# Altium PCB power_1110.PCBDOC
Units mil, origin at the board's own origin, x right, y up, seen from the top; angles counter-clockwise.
Board outline 4331.71 x 2363.2 mil, 4 copper layers (TOP, GND02, POWER03, BOTTOM), stack 28.8 mil thick; 43 components, 17 nets, 191 pads, 290 vias.
Unrouted connection lines stored in the file: 131.
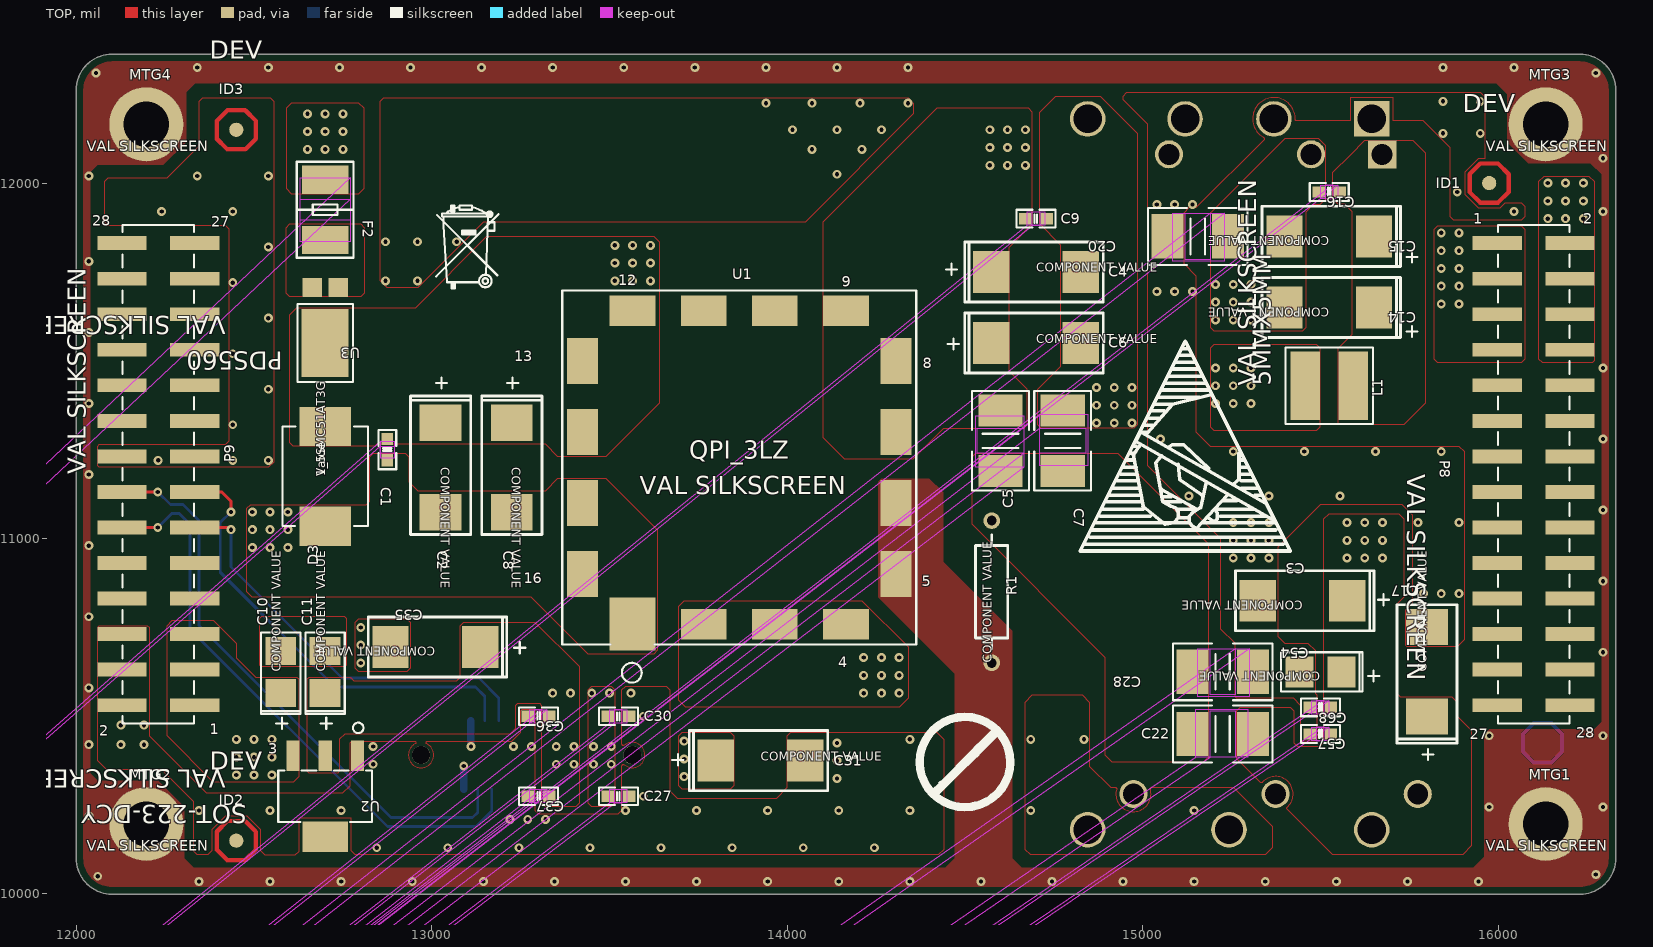
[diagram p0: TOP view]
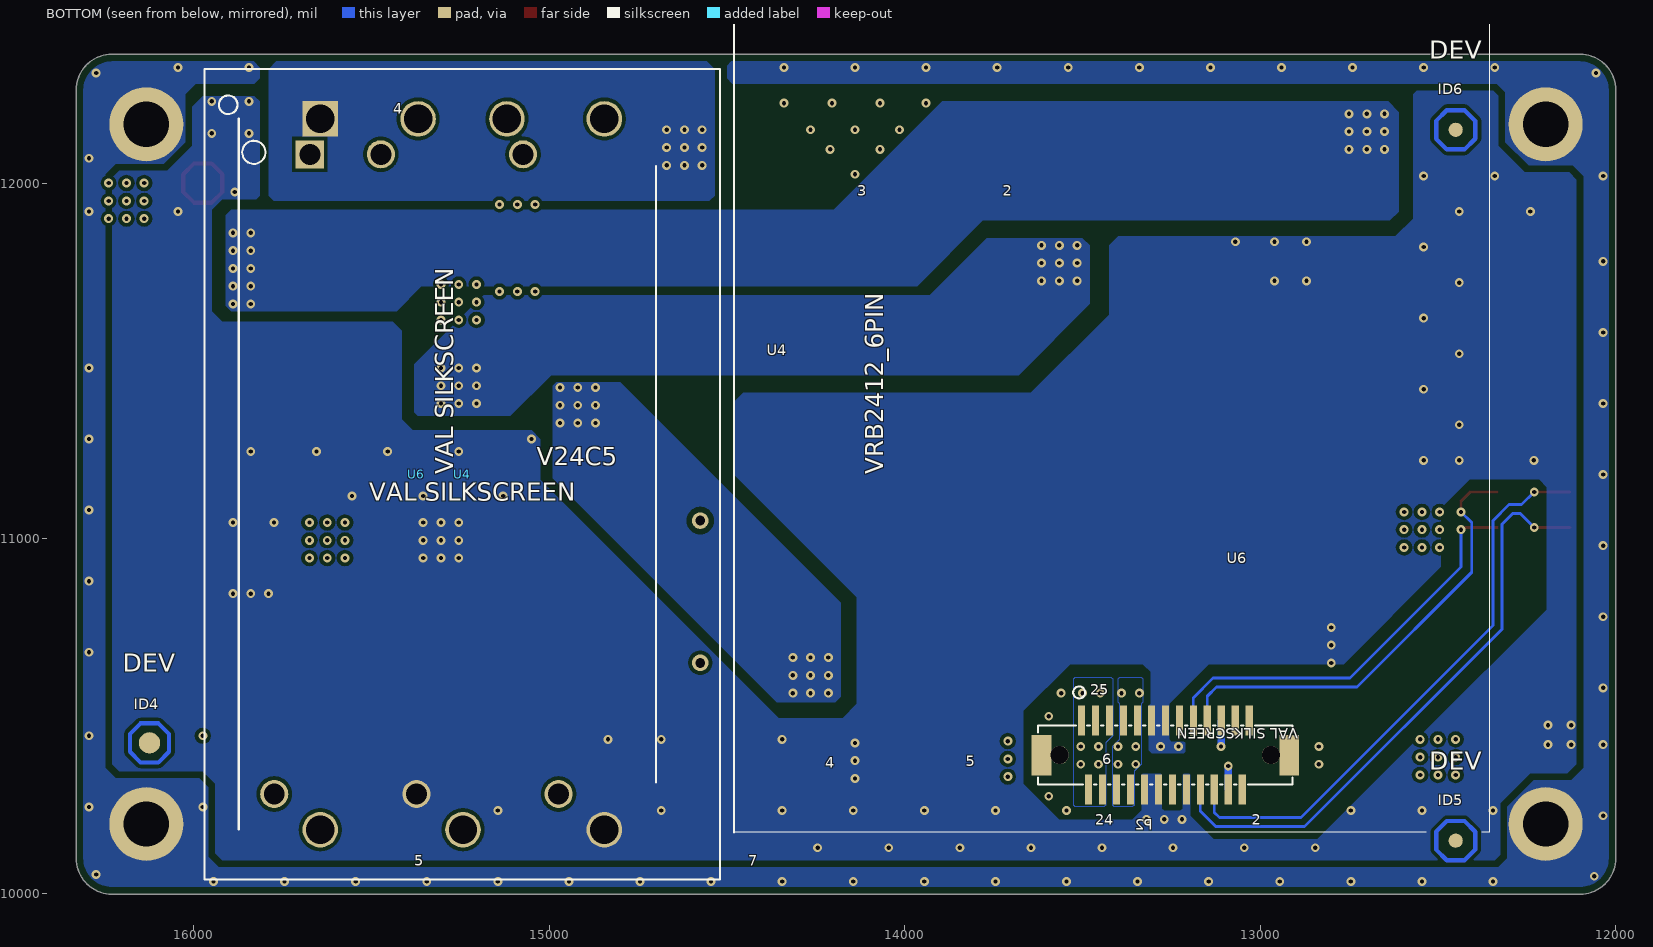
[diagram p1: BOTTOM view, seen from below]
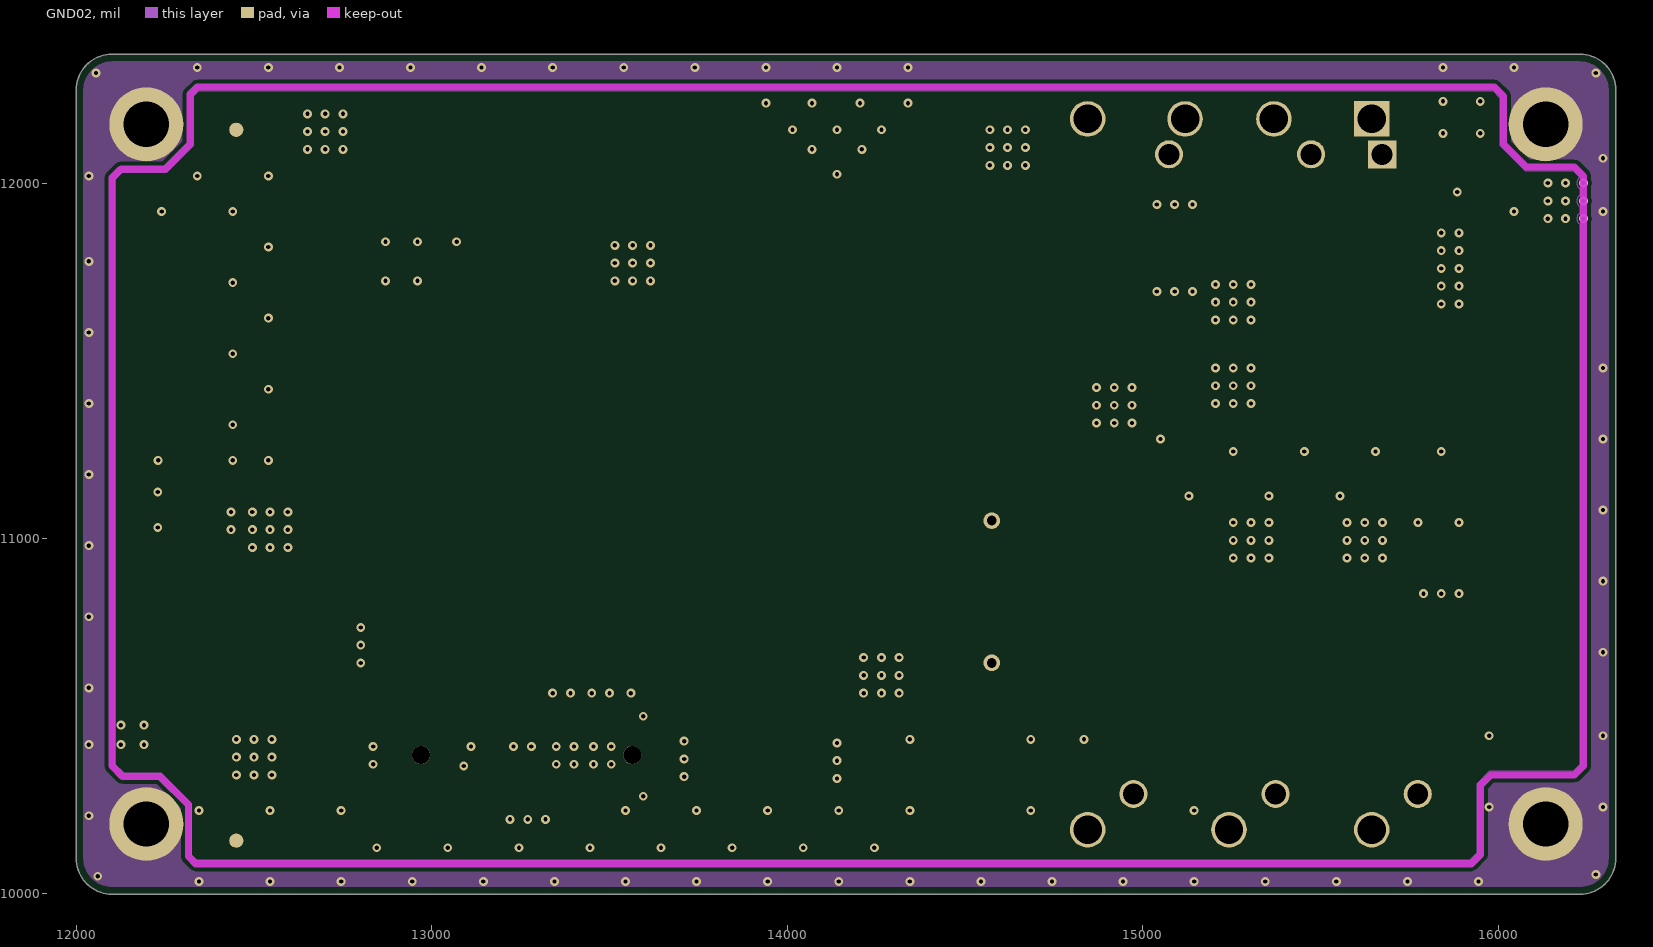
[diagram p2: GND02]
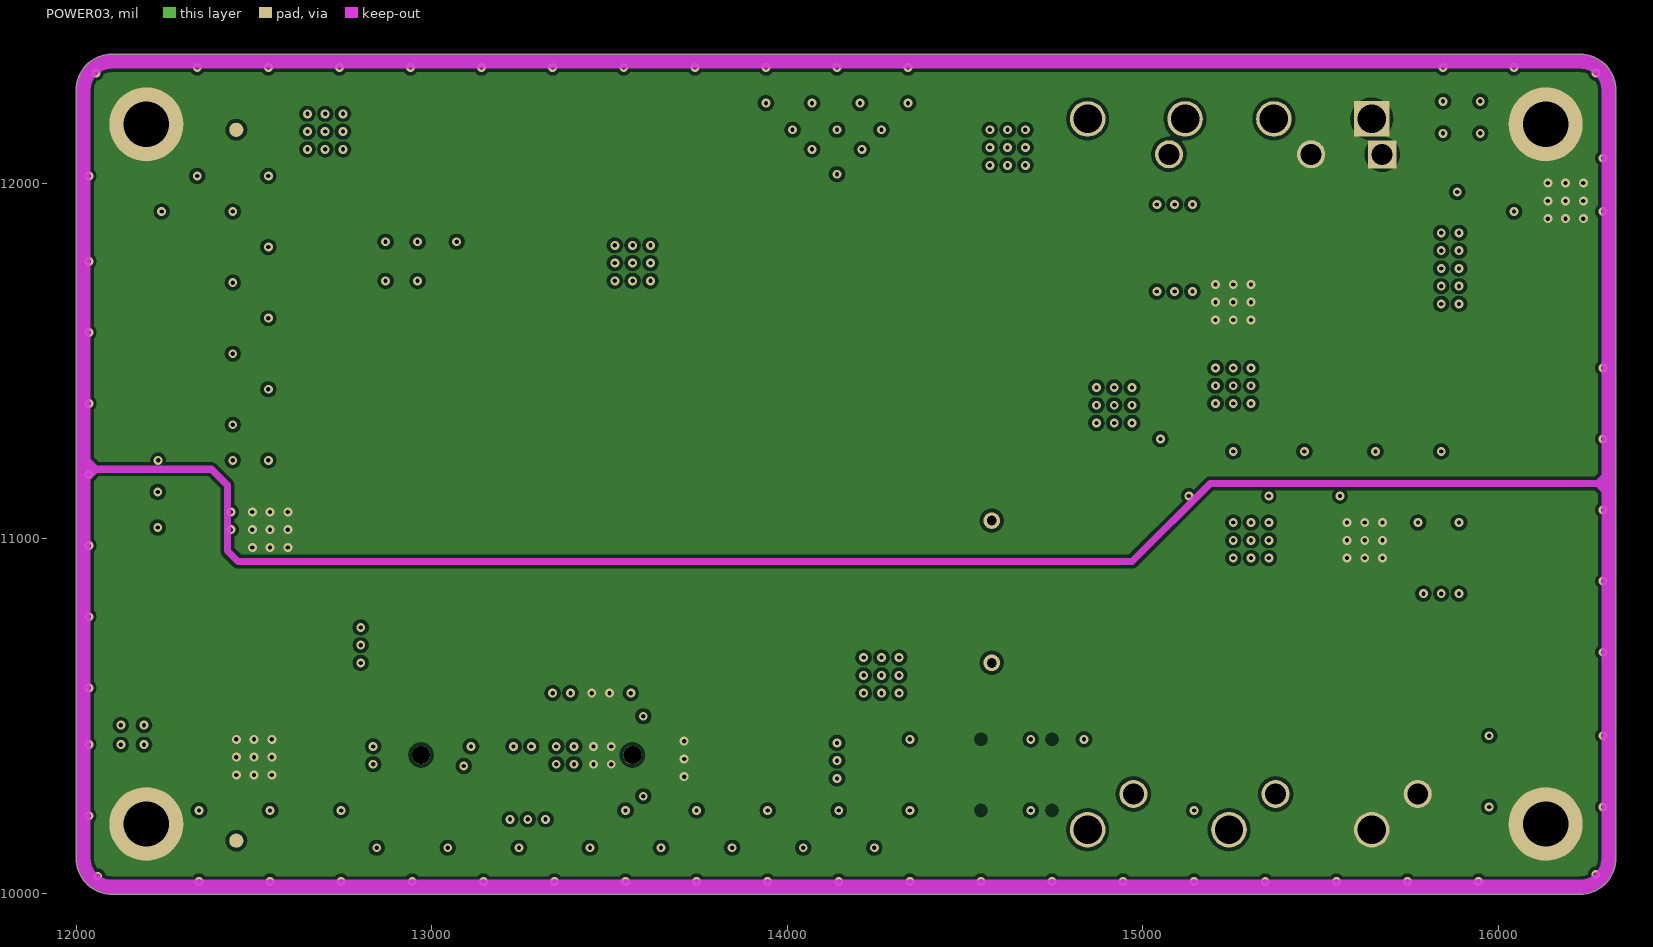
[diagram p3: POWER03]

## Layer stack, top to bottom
TOP: signal copper 1.2
Dielectric: core 8, FR-4, Dk 4.5
GND02: signal copper 1.2
Dielectric: core 8, FR-4, Dk 4.5
POWER03: signal copper 1.2
Dielectric: core 8, FR-4, Dk 4.5
BOTTOM: signal copper 1.2

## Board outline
11999.5,10100 ccw(c12100,10100) 12100,9999.5 16230.71,9999.5 ccw(c16230.71,10100) 16331.21,10100 16331.21,12262.2 ccw(c16230.71,12262.2) 16230.71,12362.7 12100,12362.7 ccw(c12100,12262.2) 11999.5,12262.2

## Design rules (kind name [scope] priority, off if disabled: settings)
Clearance [All] p1: gap=10
PlaneConnect [All] p1: planeconnectstyle=Direct reliefexpansion=20 reliefentries=4 reliefconductorwidth=10 reliefairgap=10
PolygonConnect [All] p1: connectstyle=Direct reliefconductorwidth=10 reliefentries=4 polygonreliefangle="90 Angle"
RoomDefinition CompsKeepin0 [All vs False] p1: confinementstyle=ConfineIn formatcopy=TRUE lockcomponents=FALSE outline 12100,10040 12094.77,10040.23 12089.58,10040.91 12084.47,10042.04 12079.48,10043.62 12074.64,10045.62 12070,10048.04 12065.59,10050.85 12061.43,10054.04 12057.57,10057.57 12054.04,10061.43 12050.85,10065.59 12048.04,10070 12045.62,10074.64 12043.62,10079.48 12042.04,10084.47 12040.91,10089.58 12040.23,10094.77 12040,10100 12040,12262.2 12040.23,12267.43 12040.91,12272.62 12042.04,12277.73 12043.62,12282.73 12045.62,12287.56 12048.04,12292.2 12050.85,12296.62 12054.04,12300.77 12057.57,12304.63 12061.43,12308.17 12065.59,12311.35 12070,12314.17 12074.64,12316.58 12079.48,12318.59 12084.47,12320.16 12089.58,12321.29 12094.77,12321.98 12100,12322.2 16230.71,12322.2 16235.94,12321.98 16241.13,12321.29 16246.24,12320.16 16251.23,12318.59 16256.07,12316.58 16260.71,12314.17 16265.12,12311.35 16269.28,12308.17 16273.14,12304.63 16276.67,12300.77 16279.86,12296.62 16282.67,12292.2 16285.09,12287.56 16287.09,12282.73 16288.66,12277.73 16289.8,12272.62 16290.48,12267.43 16290.71,12262.2 16290.71,10100 16290.48,10094.77 16289.8,10089.58 16288.66,10084.47 16287.09,10079.48 16285.09,10074.64 16282.67,10070 16279.86,10065.59 16276.67,10061.43 16273.14,10057.57 16269.28,10054.04 16265.12,10050.85 16260.71,10048.04 16256.07,10045.62 16251.23,10043.62 16246.24,10042.04 16241.13,10040.91 16235.94,10040.23 16230.71,10040 12100,10040
RoutingVias [All] p1: holewidth=28 width=50 viastyle="Through Hole" minholewidth=28 minwidth=50 maxholewidth=28 maxwidth=50
SilkscreenOverComponentPads [All] p1: minsilkscreentomaskgap=10
SolderMaskExpansion [All] p1: expansion=4
TestPointUsage [All] p1: valid=0 allowmultiple=FALSE
Testpoint [All] p1: side=15 testpointundercomponent=TRUE minsize=40 maxsize=100 preferedsize=60 minholesize=0 maxholesize=40 preferedholesize=32 testpointgrid=1 style=1023 order=0123456789
Width [All] p1: maxlimit=10 minlimit=10 preferedwidth=10 impedancedriven=TRUE minimp=20.320000 maximp=37.470000 favimp=17.700000
22 further rules are at their usual default settings.

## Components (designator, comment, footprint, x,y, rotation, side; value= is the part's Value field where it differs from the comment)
C1 "0603C" 0603C#1 12875,11250 r270 top
C2 "7343T" 7343T 13041.73,11219.68 r270 top
C3 "7343T" 7343T 15469.68,10808.27 r180 top
C4 "7343T" 7343T 14680.32,11766.73 r0 top
C5 "1812C" 1812C#1 14600,11275 r90 top
C6 "7343T" 7343T 14680.32,11566.73 r0 top
C7 "1812C" 1812C#2 14775,11275 r270 top
C8 "7343T" 7343T 13241.73,11219.68 r270 top
C9 "0603C" 0603C#2 14700,11900 r0 top
C10 "3528T" 3528T 12561.22,10607.29 r90 top
C11 "3528T" 3528T 12686.22,10607.29 r90 top
C14 "7343T" 7343T 15544.68,11633.27 r180 top
C15 "7343T" 7343T 15544.68,11833.27 r180 top
C16 "0603C" 0603C#3 15525,11975 r180 top
C17 "7343T" 7343T 15783.27,10605.32 r90 top
C20 "1812C" 1812C#3 15155,11850 r180 top
C22 "1812C" 1812C#1 15225,10450 r0 top
C27 "0603C" 0603C#2 13525,10275 r0 top
C28 "1812C" 1812C#4 15225,10625 r180 top
C30 "0603C" 0603C#2 13525,10500 r0 top
C31 "7343T" 7343T 13905.32,10391.73 r0 top
C35 "7343T" 7343T 13029.68,10678.27 r180 top
C36 "0603C" 0603C#4 13300,10500 r180 top
C37 "0603C" 0603C#4 13300,10275 r180 top
C54 "3528T" 3528T 15517.71,10611.22 r180 top
C57 "0603C" 0603C#5 15500,10450 r180 top
C68 "0603C" 0603C#5 15500,10525 r180 top
D3 "1_5SMC51AT3G" 1_5SMC51AT3G 12698.58,11174.4 r90 top
F2 "1812F" 1812F 12700,11925 r270 top
L1 "5MMX5MM" 5MMX5MM 15524.23,11429.47 r90 top
MTG1 "MTGH200C125D_PL" MTGH200C125D_PL 16133.86,10196.85 r0 top
MTG2 "MTGH200C125D_PL" MTGH200C125D_PL 12196.85,10196.85 r0 top
MTG3 "MTGH200C125D_PL" MTGH200C125D_PL 16133.86,12165.35 r0 top
MTG4 "MTGH200C125D_PL" MTGH200C125D_PL 12196.85,12165.35 r0 top
P2 "DF9_25P_1V_25PIN" DF9_25P_1V_25PIN 13266.69,10388.58 r180 bottom
P8 "HEADER14X2-2R54" HEADER14X2-2R54 16103.87,11181.1 r270 top
P9 "HEADER14X2-2R54" HEADER14X2-2R54 12226.84,11181.1 r90 top
R1 "AXIAL-0_4" AXIAL-0_4 14575.2,10850.4 r90 top
U1 "QPI_3LZ" QPI_3LZ 13866.41,11199.98 r0 top
U2 "SOT-223-DCY" SOT-223-DCY 12699.18,10272.58 r180 top
U3 "PDS560" PDS560 12698.58,11586.47 r180 top
U4 "V24C5" V24C5 15245.89,11183.07 r0 bottom
U6 "VRB2412_6PIN" VRB2412_6PIN 15374.3,11181.3 r270 bottom

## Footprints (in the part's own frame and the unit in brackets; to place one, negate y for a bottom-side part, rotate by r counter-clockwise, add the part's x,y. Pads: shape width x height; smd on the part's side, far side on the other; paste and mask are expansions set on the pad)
1_5SMC51AT3G [mil] "1_5SMC51AT3G"
  rect 110x145 smd: 1(-139.89,-1.42) 2(141.09,-1.42)
  silkscreen extent -139,-122 141,119
5MMX5MM [mil] "5MMX5MM"
  rect 193x83 smd: 1(0.53,66.32) 2(0.53,-67.86)
  silkscreen extent -107,-124 108,122
0603C#1 [mil] "0603C"
  rect 35x32 smd: 1(-30,0) 2(30,0)
  TOP keep-out region: -10,-20 -10,20 10,20 10,-20 -10,-20 11250,-12875
  TOP keep-out region: -24,-19 -24,19 24,19 24,-19 -24,-19 11250,-12875
  silkscreen extent -55,-25 55,25
0603C#2 [mil] "0603C"
  rect 35x32 smd: 1(-30,0) 2(30,0)
  TOP keep-out region: -10,-20 -10,20 10,20 10,-20 -10,-20 -14700,-11900
  TOP keep-out region: -24,-19 -24,19 24,19 24,-19 -24,-19 -14700,-11900
  silkscreen extent -55,-25 55,25
0603C#3 [mil] "0603C"
  rect 35x32 smd: 1(-30,0) 2(30,0)
  TOP keep-out region: -10,-20 -10,20 10,20 10,-20 -10,-20 15525,11975
  TOP keep-out region: -24,-19 -24,19 24,19 24,-19 -24,-19 15525,11975
  silkscreen extent -55,-25 55,25
0603C#4 [mil] "0603C"
  rect 35x32 smd: 1(-30,0) 2(30,0)
  TOP keep-out region: -10,-20 -10,20 10,20 10,-20 -10,-20 13300,10500
  TOP keep-out region: -24,-19 -24,19 24,19 24,-19 -24,-19 13300,10500
  silkscreen extent -55,-25 55,25
0603C#5 [mil] "0603C"
  rect 35x32 smd: 1(-30,0) 2(30,0)
  TOP keep-out region: -10,-20 -10,20 10,20 10,-20 -10,-20 15500,10450
  TOP keep-out region: -24,-19 -24,19 24,19 24,-19 -24,-19 15500,10450
  silkscreen extent -55,-25 55,25
1812C#1 [mil] "1812C"
  rect 90x125 smd: 1(-85,0) 2(85,0)
  TOP keep-out region: -35,-65 -35,65 35,65 35,-65 -35,-65 -11275,14600
  TOP keep-out region: -75,-65 -75,70 70,70 70,-65 -75,-65 -11275,14600
  silkscreen extent -140,-80 140,80
1812C#2 [mil] "1812C"
  rect 90x125 smd: 1(-85,0) 2(85,0)
  TOP keep-out region: -35,-65 -35,65 35,65 35,-65 -35,-65 11275,-14775
  TOP keep-out region: -75,-65 -75,70 70,70 70,-65 -75,-65 11275,-14775
  silkscreen extent -140,-80 140,80
1812C#3 [mil] "1812C"
  rect 90x125 smd: 1(-85,0) 2(85,0)
  TOP keep-out region: -35,-65 -35,65 35,65 35,-65 -35,-65 15155,11850
  TOP keep-out region: -75,-65 -75,70 70,70 70,-65 -75,-65 15155,11850
  silkscreen extent -140,-80 140,80
1812C#4 [mil] "1812C"
  rect 90x125 smd: 1(-85,0) 2(85,0)
  TOP keep-out region: -35,-65 -35,65 35,65 35,-65 -35,-65 15225,10625
  TOP keep-out region: -75,-65 -75,70 70,70 70,-65 -75,-65 15225,10625
  silkscreen extent -140,-80 140,80
1812F [mil] "1812F"
  rect 80x130 smd: 1(-85,0) 2(85,0)
  TOP keep-out region: -90,70 90,70 90,-70 -90,-70 -90,70 11925,-12700
  TOP keep-out region: -30,70 30,70 30,-70 -30,-70 -30,70 11925,-12700
  silkscreen extent -135,-80 135,80
3528T [mil] "3528T"
  rect 79x87 smd: 1(-41.34,-13.78) 2(76.77,-13.78)
  silkscreen extent -143,-69 128,41
7343T [mil] "7343T"
  rect 102x118 smd: 1(-106.3,-16.73) 2(145.66,-16.73)
  silkscreen extent -234,-101 209,68
AXIAL-0_4 [mil] "AXIAL-0_4"
  round 47 hole 28: 1(-200,-0.2) 2(200,-0.2)
  silkscreen extent -160,-45 160,45
DF9_25P_1V_25PIN [mil] "DF9_25P_1V_25PIN"
  rect 20x84 smd: 1(-236.45,99.49) 2(-216.77,-94.76) 3(-197.08,99.49) 4(-177.4,-94.76) 5(-157.71,99.49) 6(-138.03,-94.76) 7(-118.34,99.49) 8(-98.66,-94.76) 9(-78.97,99.49) 10(-59.29,-94.76) 11(-39.6,99.49) 12(-19.92,-94.76) 13(-0.23,99.49) 14(19.45,-94.76) 15(39.14,99.49) 16(58.82,-94.76) 17(78.51,99.49) 18(98.19,-94.76) 19(117.88,99.49) 20(137.57,-94.76) 21(157.25,99.49) 22(176.93,-94.76) 23(196.62,99.49) 24(216.31,-94.76) 25(235.99,99.49)
  rect 55x114 smd: 26(348.14,2.36) 27(-348.6,2.36)
  round 51 hole 51: 28(297.01,2.36) 29(-297.48,2.36)
  silkscreen extent -359,-80 358,195
HEADER14X2-2R54 [mil] "HEADER14X2-2R54"
  rect 39x138 smd: 1(-650,-106.23) 2(-650,98.49) 3(-550,-106.23) 4(-550,98.49) 5(-450,-106.23) 6(-450,98.49) 7(-350,-106.23) 8(-350,98.49) 9(-250,-106.23) 10(-250,98.49) 11(-150,-106.23) 12(-150,98.49) 13(-50,-106.23) 14(-50,98.49) 15(50,-106.23) 16(50,98.49) 17(150,-106.23) 18(150,98.49) 19(250,-106.23) 20(250,98.49) 21(350,-106.23) 22(350,98.49) 23(450,-106.23) 24(450,98.49) 25(550,-106.23) 26(550,98.49) 27(650,-106.23) 28(650,98.49)
  silkscreen extent -701,-104 701,97
MTGH200C125D_PL [mil] "MTGH200C125D_PL"
  round 208 hole 128: 1(0,0)
PDS560 [mil] "PDS560"
  rect 55x54 smd: 1(-37.64,-120.07) 2(34.8,-120.07)
  rect 132x192 smd: 3(-1.42,36.47)
  silkscreen extent -80,-73 77,146
QPI_3LZ [mil] "QPI_3LZ"
  rect 129x149 smd: 1(-301.41,-440.98)
  rect 129x86 smd: 2(-101.41,-440.98) 3(98.59,-440.98) 4(298.59,-440.98) 9(298.59,441.02) 10(98.59,441.02) 11(-101.41,441.02) 12(-301.41,441.02)
  rect 86x129 smd: 5(439.59,-299.98) 6(439.59,-99.98) 7(439.59,100.02) 8(439.59,300.02) 13(-442.41,300.02) 14(-442.41,100.02) 15(-442.41,-99.98) 16(-442.41,-299.98)
  silkscreen extent -499,-605 497,498
SOT-223-DCY [mil] "SOT-223-DCY"
  rect 37x85 smd: 1(-91.37,-116.58) 2(-0.82,-116.58) 3(89.73,-116.58)
  rect 128x85 smd: 4(-0.82,111.75)
  silkscreen extent -133,-209 131,70
V24C5 [mil] "V24C5"
  rect 100x100 hole 80: 1(398.6,-997.64)
  round 100 hole 80: 2(123.4,-997.64) 3(-126.6,-997.64) 4(-400.62,-997.64) 5(-400.62,1002.36) 6(-2.98,1002.36) 7(398.6,1002.36)
  silkscreen extent -726,-1138 724,1142
VRB2412_6PIN [mil] "VRB2412_6PIN"
  rect 79x79 hole 59: 1(-899.81,-299.72)
  round 79 hole 59: 2(-899.81,-99.72) 3(-899.81,300.28) 4(900.19,400.28) 5(900.19,0.28) 6(900.19,-399.72)
  silkscreen extent -1000,-500 1000,-425

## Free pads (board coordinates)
  round 40 all layers, no hole: 1(12450,10150) 1(12450,12150)
  round 40 smd: 1(15975,12000)
  round 60 smd far side: 1(16125,10425)

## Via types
v1: diameter 25, hole 12, TOP to BOTTOM, 290 vias

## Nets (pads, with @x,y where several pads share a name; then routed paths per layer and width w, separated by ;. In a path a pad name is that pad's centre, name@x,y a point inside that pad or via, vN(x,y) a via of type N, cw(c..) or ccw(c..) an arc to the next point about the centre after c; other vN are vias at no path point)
BUS+: C1.1 C2.1 C8.1 D3.2 L1.1 U1.12 U1.13 U1.14 U3.3
  other v1: 15205,11380 15255,11380 15305,11380 15205,11430 15255,11430 15305,11430 15205,11480 15255,11480 15305,11480 13515,11725 13565,11725 13615,11725 13515,11775 13565,11775 13615,11775 13515,11825 13565,11825 13615,11825
BUS-: C1.2 C2.2 C8.2 C14.2 C15.2 C16.2 C20.1 D3.1 P8.2 P8.4 P8.6 P8.8 U1.1 U1.15 U1.16 U6.2
  other v1: 12495,10975 12545,10975 12595,10975 12495,11025 12545,11025 12595,11025 12495,11075 12545,11075 12595,11075 15205,11615 15255,11615 15305,11615 15205,11665 15255,11665 15305,11665 15205,11715 15255,11715 15305,11715 16140,11900 16190,11900 16240,11900 16140,11950 16190,11950 16240,11950 16140,12000 16190,12000 16240,12000
GND: C3.2 C17.2 C20.2 C27.2 C28.1 C30.2 C31.2 C35.2 C36.2 C37.2 C54.2 C57.2 C68.2 P2.10 P2.11 P2.12 P2.13 P2.16 P2.21 P2.22 P9.2 P9.4 P9.6 P9.15 P9.16 U2.1 U4.5 U6.5 | length 139.6
  BOTTOM w20: P2.22 13089.76,10359.76 v1(13090,10360) ; P2.21 13109.45,10415.55 v1(13110,10415)
  other v1: 12845,10130 13045,10130 13245,10130 13445,10130 13645,10130 13845,10130 14045,10130 14245,10130 13220,10210 13270,10210 13320,10210 12345,10235 12545,10235 12745,10235 13545,10235 13745,10235 13945,10235 14145,10235 14345,10235 14685,10235 15145,10235 13595,10275 14140,10325 12835,10365 14140,10375 12835,10415 13230,10415 13280,10415 12125,10420 12190,10420 14140,10425 14345,10435 14685,10435 14835,10435 12125,10475 12190,10475 13595,10500 13560,10565 12800,10650 12800,10700 12800,10750 15790,10845 15840,10845 15890,10845 15255,10945 15305,10945 15355,10945 15255,10995 15305,10995 15355,10995 15255,11045 15305,11045 15355,11045 15775,11045 15890,11045 15130,11120 15355,11120 15555,11120 12230,11220 12440,11220 12540,11220 15255,11245 15455,11245 15655,11245 15840,11245 15050,11280 12440,11320 12540,11420 12440,11520 12540,11620 15040,11695 15090,11695 15140,11695 12440,11720 12870,11725 12960,11725 12540,11820 12870,11835 12960,11835 13070,11835 12240,11920 12440,11920 16045,11920 15040,11940 15090,11940 15140,11940 15885,11975 12340,12020 12540,12020 14140,12025 14070,12095 14210,12095 15845,12140 15950,12140 14015,12150 14140,12150 14265,12150 13940,12225 14070,12225 14205,12225 14340,12225 15845,12230 15950,12230
NETC10_2: C10.2 C11.2
NETC14_1: C14.1 C15.1 C16.1 L1.2 U6.1
NETF2_2: F2.2 U3.1 U3.2
QPI+: C4.1 C5.2 C6.1 C9.1 U1.7 U1.8 U1.9 U4.1
  other v1: 14570,12050 14620,12050 14670,12050 14570,12100 14620,12100 14670,12100 14570,12150 14620,12150 14670,12150
QPI-: C4.2 C6.2 C7.1 C9.2 U1.2 U1.3 U1.4 U4.4
  other v1: 14215,10565 14265,10565 14315,10565 14215,10615 14265,10615 14315,10615 14215,10665 14265,10665 14315,10665 14870,11325 14920,11325 14970,11325 14870,11375 14920,11375 14970,11375 14870,11425 14920,11425 14970,11425
RX_BD: P2.18 P9.12 | length 1672.5
  TOP w8: P9.12 v1(12228.9,11031.1)
  BOTTOM w8: v1(12228.9,11031.1) 12268.45,11070.66 12289.34,11070.66 12320,11040 12320,10745 12875,10190 13125,10190 13168.5,10233.5 P2.18
RX_GPS: P2.17 P9.11 | length 1178.9
  TOP w8: P9.11 12428.9,11031.1 v1(12435,11025)
  BOTTOM w8: v1(12435,11025) 12435,10920 12747.75,10607.25 13132.75,10607.25 13188.19,10551.81 P2.17
SHIELD: MTG1.1 MTG2.1 MTG3.1 MTG4.1 R1.1 U1.5 U1.6
  other v1: 12345,10035 12545,10035 12745,10035 12945,10035 13145,10035 13345,10035 13545,10035 13745,10035 13945,10035 14145,10035 14345,10035 14545,10035 14745,10035 14945,10035 15145,10035 15345,10035 15545,10035 15745,10035 15945,10035 12060,10050 16275,10055 12035,10220 15975,10245 16295,10245 12035,10420 15975,10445 16295,10445 12035,10580 16295,10680 12035,10780 16295,10880 12035,10980 16295,11080 12035,11180 16295,11280 12035,11380 16295,11480 12035,11580 12035,11780 16295,11920 12035,12020 16295,12070 12055,12310 16275,12310 12340,12325 12540,12325 12740,12325 12940,12325 13140,12325 13340,12325 13540,12325 13740,12325 13940,12325 14140,12325 14340,12325 15845,12325 16045,12325
SURFACE: C5.1 C7.2 C22.1 C28.2 R1.2
TX_BD: P2.20 P9.14 | length 1623.8
  TOP w8: P9.14 v1(12228.9,11131.1)
  BOTTOM w8: v1(12228.9,11131.1) 12264.59,11095.41 12299.59,11095.41 12344.75,11050.25 12344.75,10755.25 12885.25,10214.75 13114.75,10214.75 13129.13,10229.13 P2.20
TX_GPS: P2.19 P9.13 | length 1281.6
  TOP w8: P9.13 12408.9,11131.1 12435,11105 v1(12435,11075)
  BOTTOM w8: v1(12435,11075) 12405,11045 12405,10905 12727.5,10582.5 13122.5,10582.5 13148.82,10556.18 P2.19
VBUSXX+: F2.1 P8.1 P8.3 P8.5 P8.7
  other v1: 15840,11660 15890,11660 15840,11710 15890,11710 15840,11760 15890,11760 15840,11810 15890,11810 15840,11860 15890,11860 12650,12095 12700,12095 12750,12095 12650,12145 12700,12145 12750,12145 12650,12195 12700,12195 12750,12195
VDD_5V0: C11.1 C35.1 C36.1 C37.1 P2.6 P2.7 P2.8 P2.9 U2.2
  other v1: 13350,10365 13400,10365 13350,10415 13400,10415 13340,10565 13390,10565
VDD_12V: C3.1 C10.1 C17.1 C22.2 C27.1 C30.1 C31.1 C54.1 C57.1 C68.1 P2.1 P2.2 P2.3 P2.4 P2.5 P9.1 P9.3 P9.5 U2.3 U4.7 U6.6
  other v1: 13710,10330 12450,10335 12500,10335 12550,10335 13455,10365 13505,10365 13710,10380 12450,10385 12500,10385 12550,10385 13455,10415 13505,10415 13710,10430 12450,10435 12500,10435 12550,10435 13450,10565 13500,10565 15575,10945 15625,10945 15675,10945 15575,10995 15625,10995 15675,10995 15575,11045 15625,11045 15675,11045
pads on no net: P2.14 P2.15 P2.23 P2.24 P2.25 P2.26 P2.27 P2.28 P2.29 P8.9 P8.10 P8.11 P8.12 P8.13 P8.14 P8.15 P8.16 P8.17 P8.18 P8.19 P8.20 P8.21 P8.22 P8.23 P8.24 P8.25 P8.26 P8.27 P8.28 P9.7 P9.8 P9.9 P9.10 P9.17 P9.18 P9.19 P9.20 P9.21 P9.22 P9.23 P9.24 P9.25 P9.26 P9.27 P9.28 U1.10 U1.11 U2.4 U4.2 U4.3 U4.6 U6.3 U6.4
copper on no net: | length 2218.2
  TOP w12: 12395,10125 12425,10095 12475,10095 12505,10125 12505,10175 12475,10205 12425,10205 12395,10175 12395,10125 ; 12395,12125 12425,12095 12475,12095 12505,12125 12505,12175 12475,12205 12425,12205 12395,12175 12395,12125 ; 15920,11975 15950,11945 16000,11945 16030,11975 16030,12025 16000,12055 15950,12055 15920,12025 15920,11975
  BOTTOM w12: 12395,10125 12425,10095 12475,10095 12505,10125 12505,10175 12475,10205 12425,10205 12395,10175 12395,10125 ; 12395,12125 12425,12095 12475,12095 12505,12125 12505,12175 12475,12205 12425,12205 12395,12175 12395,12125 ; 16070,10400 16100,10370 16150,10370 16180,10400 16180,10450 16150,10480 16100,10480 16070,10450 16070,10400

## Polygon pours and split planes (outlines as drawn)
VDD_12V on TOP (solid): 13705,10455 13840,10455 13850,10445 13850,10305 13840,10295 13705,10295 13695,10305 13695,10445 13705,10455
VDD_12V on TOP (solid): 13450,10585 13505,10585 13515,10575 13515,10255 13505,10245 13450,10245 13440,10255 13440,10575 13450,10585
VDD_12V on TOP (solid): 12270,10770 12345,10770 12385,10770 12450,10705 12450,10665 12505,10610 12620,10610 12625,10605 12625,10330 12610,10315 12385,10315 12255,10445 12255,10755 12270,10770
VDD_12V on TOP (solid): 107 vertices, not listed, extent 15265,10110 15925,11070
VDD_5V0 on TOP (solid): 32 vertices, not listed, extent 12650,10245 13415,10765
VBUSXX+ on TOP (solid): 12625,11970 12775,11970 12795,11970 12810,11985 12810,12210 12795,12225 12775,12225 12625,12225 12605,12225 12590,12210 12590,11985 12605,11970 12625,11970
VBUSXX+ on TOP (solid): 15875,11880 16065,11880 16075,11870 16075,11505 16065,11495 15880,11495 15830,11495 15820,11505 15820,11870 15830,11880 15875,11880
SURFACE on TOP (solid): 14930,11240 15185,10985 15185,10385 15170,10370 14980,10370 14915,10370 14895,10390 14895,10665 14520,11040 14520,11115 14520,11230 14530,11240 14930,11240
SHIELD on TOP (solid): 82 vertices, not listed, extent 12020,10020 16310.71,12342.2
QPI- on TOP (solid): 20 vertices, not listed, extent 14705,11310 14985,12245
QPI- on TOP (solid): 13710,10825 14210,10825 14340,10695 14340,10615 14340,10550 14315,10525 13715,10525 13695,10545 13695,10625 13695,10810 13710,10825
QPI+ on TOP (solid): 21 vertices, not listed, extent 14100,11225 14690,12210
NETC10_2 on TOP (solid): 12520,10640 12755,10640 12760,10645 12760,10775 12755,10780 12520,10780 12515,10775 12515,10645 12520,10640
NETC14_1 on TOP (solid): 20 vertices, not listed, extent 15535,11320 15795,12120
NETF2_2 on TOP (solid): 12765,11680 12620,11680 12600,11680 12590,11690 12590,11875 12600,11885 12625,11885 12735,11885 12775,11885 12800,11885 12810,11875 12810,11690 12800,11680 12780,11680 12765,11680
GND on TOP (solid): 307 vertices, not listed, extent 12060,10108.33 14440,10755
GND on TOP (solid): 105 vertices, not listed, extent 14670,10110 15365,10560
GND on TOP (solid): 12855,11910 12855,12220 12855,12230 12865,12240 14340,12240 14355,12225 14355,12195 14050,11890 13145,11890 12960,11705 12875,11705 12855,11725 12855,11910
GND on TOP (solid): 24 vertices, not listed, extent 12060,11200 12555,12240
GND on TOP (solid): 169 vertices, not listed, extent 14945,10430 16075,12255
GND on TOP (solid): 12795,10775 12930,10775 12940,10765 12940,10635 12930,10625 12795,10625 12785,10635 12785,10765 12795,10775
BUS- on TOP (solid): 16125,11495 16115,11505 16115,12005 16130,12020 16255,12020 16270,12005 16270,11500 16265,11495 16125,11495
BUS- on TOP (solid): 17 vertices, not listed, extent 15190,11585 15515,12125
BUS- on TOP (solid): 25 vertices, not listed, extent 12480,10675 13635,11240
BUS+ on TOP (solid): 22 vertices, not listed, extent 12600,11230 13640,11850
BUS+ on TOP (solid): 15490,11545 15200,11545 15190,11535 15190,11315 15200,11305 15490,11305 15500,11315 15500,11535 15490,11545
SHIELD on GND02 (solid): 82 vertices, not listed, extent 12020,10020 16310.7,12342.2
GND on GND02 (solid): 120 vertices, not listed, extent 12110,10095 16230,12260
VDD_12V on POWER03 (solid): 1076 vertices, not listed, extent 12040,10040 16290.71,11185
BUS- on POWER03 (solid): 1081 vertices, not listed, extent 12040,10945 16290.71,12322.2
VDD_12V on BOTTOM (solid): 13415,10605 13415,10445 13435,10425 13435,10250 13440,10245 13520,10245 13525,10250 13525,10605 13520,10610 13420,10610 13415,10605
VDD_5V0 on BOTTOM (solid): 22 vertices, not listed, extent 13330,10245 13415,10610
VBUSXX+ on BOTTOM (solid): 364 vertices, not listed, extent 12610,11640 15910,12230
SHIELD on BOTTOM (solid): 192 vertices, not listed, extent 12020,10020 16310.71,12342.2
QPI- on BOTTOM (solid): 14800,11440 14980,11440 14990,11430 14990,11170 14360,10540 14195,10540 14180,10555 14180,10820 14800,11440
QPI+ on BOTTOM (solid): 88 vertices, not listed, extent 14535,11950 15790,12342.2
GND on BOTTOM (solid): 213 vertices, not listed, extent 12110.43,10095 16230,12260
BUS+ on BOTTOM (solid): 168 vertices, not listed, extent 13480,11345 15380,11845
no net on Top Overlay (solid): 14638.11,10371.04 ccw(c14500.05,10371.04) 14500.05,10509.1 ccw(c14500.05,10371.04) 14361.98,10371.04 ccw(c14500.05,10371.04) 14500.05,10232.98 ccw(c14500.05,10371.04) 14638.11,10371.04
no net on Top Overlay (solid): 47 vertices, not listed, extent 14525.35,10311.09 14597.87,10435.37
no net on Top Overlay (solid): 33 vertices, not listed, extent 14414.06,10312.52 14507.4,10435.37
no net on Top Overlay (solid): 14638.11,10371.04 ccw(c14500.05,10371.04) 14500.05,10509.1 ccw(c14500.05,10371.04) 14361.98,10371.04 ccw(c14500.05,10371.04) 14500.05,10232.98 ccw(c14500.05,10371.04) 14638.11,10371.04
no net on Top Overlay (solid): 47 vertices, not listed, extent 14525.35,10311.09 14597.87,10435.37
no net on Top Overlay (solid): 33 vertices, not listed, extent 14414.06,10312.52 14507.4,10435.37
no net on PLACE_BOUND_BOTTOM (solid): 16145,10405 16145,10445 16105,10445 16105,10405 16145,10405
no net on PLACE_BOUND_BOTTOM (solid): 12470,10130 12470,10170 12430,10170 12430,10130 12470,10130
no net on PLACE_BOUND_BOTTOM (solid): 12470,12130 12470,12170 12430,12170 12430,12130 12470,12130

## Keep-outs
GND02:
  lines w20: 12100,10360 12130,10330 12235,10330 12315,10250 12315,10105 12335,10085 15925,10085 15950,10110 15950,10305 15980,10335 16215,10335 16240,10360 16240,12020 16215,12045 16080,12045 16015,12110 16015,12245 15990,12270 12340,12270 12320,12250 12320,12110 12250,12040 12125,12040 12100,12015 12100,10360
POWER03:
  lines w20: 12030,11185 12030,11205 12035,11200 12035,11195 12025,11195 12020,11190 12020,11175 12025,11170 12030,11170 12055,11195 12025,11225 12020,11220 12020,11195 12380,11195 12425,11150 12425,10965 12455,10935 14970,10935 15190,11155 16305,11155 ; 16305,11155 16305,11180 16280,11155 16300,11135 16305,11135 16305,11155
  lines w40: 12020,10100 ccw(c12100,10100) 12100,10020 16230.71,10020 ccw(c16230.71,10100) 16310.71,10100 16310.71,12262.2 ccw(c16230.71,12262.2) 16230.71,12342.2 12100,12342.2 ccw(c12100,12262.2) 12020,12262.2 12020,10100

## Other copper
TOP:
  pour cut-out: 14445,10075 12330,10075 12305,10100 12305,10245 12230,10320 12060,10320 12040,10340 12040,12030 12060,12050 12245,12050 12310,12115 12310,12255 12335,12280 15995,12280 16025,12250 16025,12115 16085,12055 16260,12055 16290,12025 16290,10485 16270,10465 15975,10465 15960,10450 15960,10105 15930,10075 14660,10075 14635,10100 14635,10740 14440,10935 14440,11130 14400,11170 14265,11170 14255,11160 14255,10835 14470,10620 14470,10100 14445,10075 0,0
  pour cut-out: 15302.93,10180.71 15302.87,10183.33 15302.7,10185.94 15302.41,10188.54 15302.01,10191.13 15301.5,10193.7 15300.88,10196.24 15300.15,10198.76 15299.31,10201.24 15298.36,10203.68 15297.3,10206.07 15296.15,10208.42 15294.89,10210.72 15293.53,10212.96 15292.07,10215.13 15290.52,10217.25 15288.88,10219.29 15287.16,10221.26 15285.35,10223.15 15283.46,10224.96 15281.49,10226.68 15279.45,10228.32 15277.33,10229.87 15275.16,10231.33 15272.92,10232.69 15270.62,10233.94 15268.27,10235.1 15265.88,10236.16 15263.44,10237.11 15260.96,10237.95 15258.44,10238.68 15255.9,10239.3 15253.33,10239.81 15250.74,10240.21 15248.14,10240.5 15245.53,10240.67 15242.91,10240.73 15240.29,10240.67 15237.68,10240.5 15235.08,10240.21 15232.49,10239.81 15229.92,10239.3 15227.38,10238.68 15224.86,10237.95 15222.38,10237.11 15219.94,10236.16 15217.54,10235.1 15215.2,10233.94 15212.9,10232.69 15210.66,10231.33 15208.48,10229.87 15206.37,10228.32 15204.33,10226.68 15202.36,10224.96 15200.47,10223.15 15198.66,10221.26 15196.93,10219.29 15195.29,10217.25 15193.75,10215.13 15192.29,10212.96 15190.93,10210.72 15189.67,10208.42 15188.51,10206.07 15187.46,10203.68 15186.51,10201.24 15185.67,10198.76 15184.94,10196.24 15184.31,10193.7 15183.8,10191.13 15183.41,10188.54 15183.12,10185.94 15182.95,10183.33 15182.89,10180.71 15182.95,10178.09 15183.12,10175.48 15183.41,10172.88 15183.8,10170.29 15184.31,10167.72 15184.94,10165.18 15185.67,10162.66 15186.51,10160.18 15187.46,10157.74 15188.51,10155.34 15189.67,10153 15190.93,10150.7 15192.29,10148.46 15193.75,10146.28 15195.29,10144.17 15196.93,10142.13 15198.66,10140.16 15200.47,10138.27 15202.36,10136.46 15204.33,10134.73 15206.37,10133.09 15208.48,10131.55 15210.66,10130.09 15212.9,10128.73 15215.2,10127.47 15217.54,10126.31 15219.94,10125.26 15222.38,10124.31 15224.86,10123.47 15227.38,10122.74 15229.92,10122.11 15232.49,10121.6 15235.08,10121.21 15237.68,10120.92 15240.29,10120.75 15242.91,10120.69 15245.53,10120.75 15248.14,10120.92 15250.74,10121.21 15253.33,10121.6 15255.9,10122.11 15258.44,10122.74 15260.96,10123.47 15263.44,10124.31 15265.88,10125.26 15268.27,10126.31 15270.62,10127.47 15272.92,10128.73 15275.16,10130.09 15277.33,10131.55 15279.45,10133.09 15281.49,10134.73 15283.46,10136.46 15285.35,10138.27 15287.16,10140.16 15288.88,10142.13 15290.52,10144.17 15292.07,10146.28 15293.53,10148.46 15294.89,10150.7 15296.15,10153 15297.3,10155.34 15298.36,10157.74 15299.31,10160.18 15300.15,10162.66 15300.88,10165.18 15301.5,10167.72 15302.01,10170.29 15302.41,10172.88 15302.7,10175.48 15302.87,10178.09 15302.93,10180.71
  pour cut-out: 12480.8,12081 12419.2,12081 12381,12119.2 12381,12180.8 12419.2,12219 12480.8,12219 12519,12180.8 12519,12119.2 12480.8,12081 0,0
  pour cut-out: 193 vertices and 0 holes, not listed, extent 0,0 15179.26,12240.68
  text "POWER V1 ARTWORK TOP" at 12905,9635 h100
GND02:
  drawing of 140 lines, arcs and shapes, not listed
  text "POWER V1 GROUND PLANE02" at 12925,9620 h100
POWER03:
  drawing of 197 lines, arcs and shapes, not listed
  text "POWER V1 POWER PLANE03" at 12975,9625 h100
BOTTOM:
  drawing of 48 lines, arcs and shapes, not listed
  text "POWER V1 ARTWORK BOTTOM" at 15180,9610 h100

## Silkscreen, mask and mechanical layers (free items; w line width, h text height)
Top Overlay:
  drawing of 316 lines, arcs and shapes, not listed
  text "3" at 15747.01,21522.01 h125
  text "3" at 15747.01,21522.02 h125
  text "3" at 15747.01,21522.01 h125
  text "3" at 15747.01,21522.02 h125
  text "5" at 21396.61,21522.02 h125
  text "5" at 21396.61,21522.02 h125
  text "1" at 10116.41,21518.76 h125
  text "1" at 10116.41,21518.76 h125
  text "4" at 18567.2,21518.76 h125
  text "4" at 18567.2,21518.76 h125
  text "7" at 27049.48,21518.75 h125
  text "7" at 27049.48,21518.76 h125
  text "7" at 27049.48,21518.75 h125
  text "7" at 27049.48,21518.76 h125
  text "8" at 29974.28,21518.76 h125
  text "8" at 29974.28,21518.76 h125
  text "2" at 12922.74,21514.81 h125
  text "2" at 12922.74,21514.8 h125
  text "2" at 12922.74,21514.81 h125
  text "2" at 12922.74,21514.8 h125
  text "6" at 24225.48,21515.22 h125
  text "6" at 24225.48,21515.22 h125
  text "6" at 24225.48,21515.22 h125
  text "6" at 24225.48,21515.22 h125
  text "A" at 8574.09,20514.82 h125
  text "A" at 8574.09,20514.82 h125
  text "A" at 31369.36,20514.82 h125
  text "A" at 31369.36,20514.82 h125
  text "B" at 8581.96,18546.31 h125
  text "B" at 8581.96,18546.31 h125
  text "B" at 31377.24,18546.31 h125
  text "B" at 31377.24,18546.31 h125
  text "C" at 8593.5,16577.81 h125
  text "C" at 8593.5,16577.81 h125
  text "C" at 31388.78,16577.81 h125
  text "C" at 31388.78,16577.81 h125
  text "D" at 8577.48,14609.31 h125
  text "D" at 8577.48,14609.31 h125
  text "D" at 31372.75,14609.31 h125
  text "D" at 31372.75,14609.31 h125
  text "E" at 8589.83,12640.8 h125
  text "E" at 8589.83,12640.8 h125
  text "E" at 31385.11,12640.8 h125
  text "E" at 31385.11,12640.8 h125
  text "DEV" at 12375,12350 h51
  text "ID3" at 12400,12250 h30
  text "DEV" at 15900,12200 h51
  text "ID1" at 15825,11985 h30
  text "F" at 8589.83,10672.3 h125
  text "F" at 8589.83,10672.3 h125
  text "F" at 31385.11,10672.3 h125
  text "F" at 31385.11,10672.3 h125
  text "DEV" at 12375,10350 h51
  text "ID2" at 12400,10250 h30
  text "G" at 8586.04,8703.8 h125
  text "G" at 8586.04,8703.8 h125
  text "G" at 31381.31,8703.8 h125
  text "G" at 31381.31,8703.8 h125
  text "H" at 8581.96,6735.3 h125
  text "H" at 8581.96,6735.3 h125
  text "H" at 31377.24,6735.3 h125
  text "H" at 31377.24,6735.3 h125
  text "3" at 15747.01,5577.13 h125
  text "3" at 15747.01,5577.13 h125
  text "5" at 21396.61,5577.14 h125
  text "5" at 21396.61,5577.14 h125
  text "1" at 10116.41,5573.87 h125
  text "1" at 10116.41,5573.87 h125
  text "4" at 18567.2,5573.88 h125
  text "4" at 18567.2,5573.88 h125
  text "7" at 27049.48,5573.87 h125
  text "7" at 27049.48,5573.87 h125
  text "8" at 29874.28,5573.87 h125
  text "8" at 29874.28,5573.87 h125
  text "2" at 12922.74,5569.93 h125
  text "2" at 12922.74,5569.93 h125
  text "6" at 24225.48,5570.34 h125
  text "6" at 24225.48,5570.34 h125
Bottom Overlay:
  drawing of 13295 lines, arcs and shapes, not listed
  text "8" at 10033,21537.5 h125
  text "8" at 10033,21537.5 h125
  text "5" at 18682.66,21531.02 h125
  text "5" at 18682.66,21531.02 h125
  text "3" at 24332.26,21531.02 h125
  text "3" at 24332.26,21531.02 h125
  text "7" at 13029.79,21527.76 h125
  text "7" at 13029.79,21527.76 h125
  text "4" at 21512.07,21527.76 h125
  text "4" at 21512.07,21527.76 h125
  text "1" at 29962.86,21527.76 h125
  text "1" at 29962.86,21527.76 h125
  text "6" at 15853.79,21524.22 h125
  text "6" at 15853.79,21524.22 h125
  text "2" at 27156.53,21523.8 h125
  text "2" at 27156.53,21523.8 h125
  text "A" at 8709.91,20523.82 h125
  text "A" at 8709.91,20523.82 h125
  text "A" at 31505.18,20523.82 h125
  text "A" at 31505.18,20523.82 h125
  text "B" at 8702.03,18555.31 h125
  text "B" at 8702.03,18555.31 h125
  text "B" at 31497.31,18555.31 h125
  text "B" at 31497.31,18555.31 h125
  text "C" at 8690.49,16586.81 h125
  text "C" at 8690.49,16586.81 h125
  text "C" at 31485.77,16586.81 h125
  text "C" at 31485.77,16586.81 h125
  text "D" at 8706.52,14618.31 h125
  text "D" at 8706.52,14618.31 h125
  text "D" at 31501.79,14618.31 h125
  text "D" at 31501.79,14618.31 h125
  text "E" at 8694.16,12649.8 h125
  text "E" at 8694.16,12649.8 h125
  text "E" at 31489.44,12649.8 h125
  text "E" at 31489.44,12649.8 h125
  text "DEV" at 12525,12350 h51
  text "ID6" at 12500,12250 h30
  text "F" at 8694.16,10681.3 h125
  text "F" at 8694.16,10681.3 h125
  text "F" at 31489.44,10681.3 h125
  text "F" at 31489.44,10681.3 h125
  text "DEV" at 16200,10625 h51
  text "ID4" at 16170,10520 h30
  text "DEV" at 12525,10350 h51
  text "ID5" at 12500,10250 h30
  text "G" at 8697.96,8712.8 h125
  text "G" at 8697.96,8712.8 h125
  text "G" at 31493.23,8712.8 h125
  text "G" at 31493.23,8712.8 h125
  text "H" at 8702.03,6744.3 h125
  text "H" at 8702.03,6744.3 h125
  text "H" at 31497.31,6744.3 h125
  text "H" at 31497.31,6744.3 h125
  text "5" at 18682.66,5586.14 h125
  text "5" at 18682.66,5586.14 h125
  text "3" at 24332.26,5586.13 h125
  text "3" at 24332.26,5586.13 h125
  text "8" at 10204.99,5582.87 h125
  text "8" at 10204.99,5582.87 h125
  text "7" at 13029.79,5582.87 h125
  text "7" at 13029.79,5582.87 h125
  text "4" at 21512.07,5582.88 h125
  text "4" at 21512.07,5582.88 h125
  text "1" at 29962.86,5582.87 h125
  text "1" at 29962.86,5582.87 h125
  text "6" at 15853.79,5579.34 h125
  text "6" at 15853.79,5579.34 h125
  text "2" at 27156.53,5578.93 h125
  text "2" at 27156.53,5578.93 h125
DIMENSION:
  drawing of 8561 lines, arcs and shapes, not listed
  text "3" at 15747.01,21522.01 h125
  text "3" at 15747.01,21522.02 h125
  text "3" at 15747.01,21522.01 h125
  text "3" at 15747.01,21522.02 h125
  text "5" at 21396.61,21522.02 h125
  text "5" at 21396.61,21522.02 h125
  text "1" at 10116.41,21518.76 h125
  text "1" at 10116.41,21518.76 h125
  text "4" at 18567.2,21518.76 h125
  text "4" at 18567.2,21518.76 h125
  text "7" at 27049.48,21518.75 h125
  text "7" at 27049.48,21518.76 h125
  text "7" at 27049.48,21518.75 h125
  text "7" at 27049.48,21518.76 h125
  text "8" at 29974.28,21518.76 h125
  text "8" at 29974.28,21518.76 h125
  text "2" at 12922.74,21514.81 h125
  text "2" at 12922.74,21514.8 h125
  text "2" at 12922.74,21514.81 h125
  text "2" at 12922.74,21514.8 h125
  text "6" at 24225.48,21515.22 h125
  text "6" at 24225.48,21515.22 h125
  text "6" at 24225.48,21515.22 h125
  text "6" at 24225.48,21515.22 h125
  text "A" at 8574.09,20514.82 h125
  text "A" at 8574.09,20514.82 h125
  text "A" at 31369.36,20514.82 h125
  text "A" at 31369.36,20514.82 h125
  text "BOARD NAME:" at 24938.5,20505.5 h75
  text "BOARD LAYERS:" at 27438.5,20505.5 h75
  text "BOARD THICKNESS:" at 24938.5,20305.5 h75
  text "MM +/-10%" at 26513.5,20305.5 h75
  text "SOLDER MASK: IPC SM-840" at 27438.5,20305.5 h75
  text "SOLDER COLORS:" at 24938.5,20105.5 h75
  text "GREEN" at 26538.5,20105.5 h75
  text "RED" at 27548.5,20105.5 h75
  text "YELLOW" at 28258.5,20105.5 h75
  text "OTHER" at 29238.5,20105.5 h75
  text "SILKSCREEN COLORS:" at 24938.5,19905.5 h75
  text "WHITE" at 26538.5,19905.5 h75
  text "RED" at 27548.5,19905.5 h75
  text "YELLOW" at 28258.5,19905.5 h75
  text "OTHER" at 29238.5,19905.5 h75
  text "HASL(Sn/Pb)" at 26358.5,19705.5 h75
  text "IMMERSION GOLD" at 27718.5,19705.5 h75
  text "OSP" at 29298.5,19705.5 h75
  text "SURFACE FINISHED:" at 25048.5,19605.5 h75
  text "HASL(Pb-Free)" at 26378.5,19505.5 h75
  text "ENIG" at 27648.5,19505.5 h75
  text "OTHER" at 29238.5,19505.5 h75
  text "Common Tg" at 26255,19300 h75
  text "High Tg 180" at 27645,19300 h75
  text "High Tg 190" at 27645,19125 h75
  text "RCC Tg 150" at 26275,19100 h75
  text "PCB FR-4 Panel:" at 25075,19050 h75
  text "High Tg 170" at 26270,18925 h75
  text "High Tg 210" at 27645,18925 h75
  text "High Tg 175" at 26270,18750 h75
  text "CONTROL IMPEDANCE: YES" at 24938.5,18555.5 h75
  text "Pb LOGO: YES" at 27438.5,18555.5 h75
  text "B" at 8581.96,18546.31 h125
  text "B" at 8581.96,18546.31 h125
  text "B" at 31377.24,18546.31 h125
  text "B" at 31377.24,18546.31 h125
  text "SPELL MODE: 1 : 1" at 24938.5,18355.5 h75
  text "OPEN WINDOWS:  NO" at 27438.5,18355.5 h75
  text "OUTLINE PROFILE:ROUTER     BRIDGE   STAMP HOLE   V-CUT(ANGLE 30)" at 24938.5,18155.5 h75
  text "INSPECTION STANDARD:IPC-II      IPC-III      GB-4588      OTHER" at 24938.5,17955.5 h75
  text "VIA TECHNIC:ALL VIA FILLED           BY GERBER" at 24938.5,17755.5 h75
  text "PRESSFIT HOLES: NO                   YES(TOLERANCE+/-0.05mm)" at 24938.5,17555.5 h75
  text "BOW AND TWIST TOLERANCE:<=0.75%            Specify   %" at 24938.5,17355.5 h75
  text "DESIGN BY:KBPCB     E-MAIL:xxxxxx   TEL:0755-xxxxx" at 24938.5,17155.5 h75
  text "OTHER:" at 24938.5,16955.5 h75
  text "V-cut Detail:" at 27800,16775 h75
  text "MAX45" at 28300,16675 h50
  text "T" at 28575,16600 h50
  text "30" at 28301.1,16593 h50
  text "C" at 8593.5,16577.81 h125
  text "C" at 8593.5,16577.81 h125
  text "C" at 31388.78,16577.81 h125
  text "C" at 31388.78,16577.81 h125
  text "1/3T" at 28825,16525 h50
  text "MIN0.30mm MAX0.70mm" at 28825,16425 h50
  text "Impedance Control Table" at 26838.5,15435.5 h75
  text "SINGLE IMPEDANCE (+/-10)%" at 25378.5,15235.5 h75
  text "DIFF IMPEDANCE (+/-10%)" at 28338.5,15235.5 h75
  text "LAYER" at 24478.5,15035.5 h75
  text "IMPEDANCE" at 25158.5,15035.5 h75
  text "WIDTH" at 26078.5,15035.5 h75
  text "REF LAYER" at 26758.5,15035.5 h75
  text "IMPEDANCE" at 27558.5,15035.5 h75
  text "WIDTH" at 28478.5,15035.5 h75
  text "SPACE" at 29278.5,15035.5 h75
  text "REF LAYER" at 29958.5,15035.5 h75
  text "L1" at 24568.5,14855.5 h75
  text "50 OHM" at 25248.5,14855.5 h75
  text "6 Mil" at 26078.5,14855.5 h75
  text "100 OHM" at 27618.5,14855.5 h75
  text "5.5 Mil" at 28418.5,14855.5 h75
  text "9 Mil" at 29278.5,14855.5 h75
  text "L2" at 24568.5,14655.5 h75
  text "50 OHM" at 25248.5,14655.5 h75
  text "6 Mil" at 26078.5,14655.5 h75
  text "100 OHM" at 27618.5,14655.5 h75
  text "5.5 Mil" at 28418.5,14655.5 h75
  text "9 Mil" at 29278.5,14655.5 h75
  text "D" at 8577.48,14609.31 h125
  text "D" at 8577.48,14609.31 h125
  text "D" at 31372.75,14609.31 h125
  text "D" at 31372.75,14609.31 h125
  text "L3" at 24568.5,14455.5 h75
  text "50 OHM" at 25248.5,14455.5 h75
  text "6 Mil" at 26078.5,14455.5 h75
  text "100 OHM" at 27618.5,14455.5 h75
  text "5.5 Mil" at 28418.5,14455.5 h75
  text "9 Mil" at 29278.5,14455.5 h75
  text "L4" at 24568.5,14255.5 h75
  text "50 OHM" at 25248.5,14255.5 h75
  text "6 Mil" at 26078.5,14255.5 h75
  text "100 OHM" at 27618.5,14255.5 h75
  text "5.5 Mil" at 28418.5,14255.5 h75
  text "9 Mil" at 29278.5,14255.5 h75
  text "L5" at 24568.5,14055.5 h75
  text "50 OHM" at 25248.5,14055.5 h75
  text "6 Mil" at 26078.5,14055.5 h75
  text "100 OHM" at 27618.5,14055.5 h75
  text "5.5 Mil" at 28418.5,14055.5 h75
  text "9 Mil" at 29278.5,14055.5 h75
  text "L6" at 24568.5,13855.5 h75
  text "50 OHM" at 25248.5,13855.5 h75
  text "6 Mil" at 26078.5,13855.5 h75
  text "100 OHM" at 27618.5,13855.5 h75
  text "5.5 Mil" at 28418.5,13855.5 h75
  text "9 Mil" at 29278.5,13855.5 h75
  text "L7" at 24568.5,13655.5 h75
  text "50 OHM" at 25248.5,13655.5 h75
  text "6 Mil" at 26078.5,13655.5 h75
  text "100 OHM" at 27618.5,13655.5 h75
  text "5.5 Mil" at 28418.5,13655.5 h75
  text "9 Mil" at 29278.5,13655.5 h75
  text "L8" at 24568.5,13455.5 h75
  text "50 OHM" at 25248.5,13455.5 h75
  text "6 Mil" at 26078.5,13455.5 h75
  text "100 OHM" at 27618.5,13455.5 h75
  text "5.5 Mil" at 28418.5,13455.5 h75
  text "9 Mil" at 29278.5,13455.5 h75
  text "L9" at 24568.5,13255.5 h75
  text "50 OHM" at 25248.5,13255.5 h75
  text "6 Mil" at 26078.5,13255.5 h75
  text "100 OHM" at 27618.5,13255.5 h75
  text "5.5 Mil" at 28418.5,13255.5 h75
  text "9 Mil" at 29278.5,13255.5 h75
  text "L10" at 24538.5,13055.5 h75
  text "50 OHM" at 25248.5,13055.5 h75
  text "6 Mil" at 26078.5,13055.5 h75
  text "100 OHM" at 27618.5,13055.5 h75
  text "5.5 Mil" at 28418.5,13055.5 h75
  text "9 Mil" at 29278.5,13055.5 h75
  text "L11" at 24538.5,12855.5 h75
  text "50 OHM" at 25248.5,12855.5 h75
  text "6 Mil" at 26078.5,12855.5 h75
  text "100 OHM" at 27618.5,12855.5 h75
  text "5.5 Mil" at 28418.5,12855.5 h75
  text "9 Mil" at 29278.5,12855.5 h75
  text "L12" at 24538.5,12655.5 h75
  text "50 OHM" at 25248.5,12655.5 h75
  text "6 Mil" at 26078.5,12655.5 h75
  text "100 OHM" at 27618.5,12655.5 h75
  text "5.5 Mil" at 28418.5,12655.5 h75
  text "9 Mil" at 29278.5,12655.5 h75
  text "E" at 8589.83,12640.8 h125
  text "E" at 8589.83,12640.8 h125
  text "E" at 31385.11,12640.8 h125
  text "E" at 31385.11,12640.8 h125
  text "0.5 OZ   Layer1" at 29664.5,12134.5 h30
  text "Prepreg  3.9 MIl" at 25477.5,12034.5 h30
  text "0.5 OZ   Layer2" at 29664.5,11934.5 h30
  text "POWER V1 DRILL CHART" at 23145,11870 h100
  text "Core 5 MIl" at 25549.5,11834.5 h30
  text "0.5 OZ   Layer3" at 29664.5,11734.5 h30
  text "1--Gerber TOP" at 23145,11670 h100
  text "Prepreg 8 MIl" at 25513.5,11634.5 h30
  text "0.5 OZ   Layer4" at 29664.5,11534.5 h30
  text "2--GROUND PLANE02" at 23145,11470 h100
  text "Core 5 MIl" at 25549.5,11434.5 h30
  text "0.5 OZ   Layer5" at 29664.5,11334.5 h30
  text "3--POWER PLANE03" at 23145,11270 h100
  text "Prepreg 8 MIl" at 25513.5,11234.5 h30
  text "0.5 OZ   Layer6" at 29664.5,11134.5 h30
  text "4--Gerber BOTTOM" at 23145,11070 h100
  text "Core 5 MIl" at 25549.5,11034.5 h30
  text "0.5 OZ   Layer7" at 29664.5,10934.5 h30
  text "Prepreg 8 MIl" at 25513.5,10834.5 h30
  text "0.5 OZ   Layer8" at 29664.5,10734.5 h30
  text "F" at 8589.83,10672.3 h125
  text "F" at 8589.83,10672.3 h125
  text "F" at 31385.11,10672.3 h125
  text "F" at 31385.11,10672.3 h125
  text "Core 5 MIl" at 25549.5,10634.5 h30
  text "0.5 OZ   Layer9" at 29664.5,10534.5 h30
  text "Prepreg 8 MIl" at 25513.5,10434.5 h30
  text "0.5 OZ   Layer10" at 29652.5,10334.5 h30
  text "Core 5 MIl" at 25549.5,10234.5 h30
  text "0.5 OZ   Layer11" at 29652.5,10134.5 h30
  text "Prepreg  3.9 MIl" at 25477.5,10034.5 h30
  text "0.5 OZ   Layer12" at 29652.5,9934.5 h30
  text "G" at 8586.04,8703.8 h125
  text "G" at 8586.04,8703.8 h125
  text "G" at 31381.31,8703.8 h125
  text "G" at 31381.31,8703.8 h125
  text "Revision:" at 27000,6800 h90
  text "Data:" at 28100,6800 h90
  text "Designer:" at 29050,6800 h90
  text "QA:" at 30200,6800 h90
  text "H" at 8581.96,6735.3 h125
  text "H" at 8581.96,6735.3 h125
  text "H" at 31377.24,6735.3 h125
  text "H" at 31377.24,6735.3 h125
  text "1.0" at 27275,6600 h90
  text "2011-01-01" at 28100,6600 h90
  text "KBPCB010" at 29075,6600 h90
  text "KBPCB001" at 30175,6600 h90
  text "3" at 15747.01,5577.13 h125
  text "3" at 15747.01,5577.13 h125
  text "5" at 21396.61,5577.14 h125
  text "5" at 21396.61,5577.14 h125
  text "1" at 10116.41,5573.87 h125
  text "1" at 10116.41,5573.87 h125
  text "4" at 18567.2,5573.88 h125
  text "4" at 18567.2,5573.88 h125
  text "7" at 27049.48,5573.87 h125
  text "7" at 27049.48,5573.87 h125
  text "8" at 29874.28,5573.87 h125
  text "8" at 29874.28,5573.87 h125
  text "2" at 12922.74,5569.93 h125
  text "2" at 12922.74,5569.93 h125
  text "6" at 24225.48,5570.34 h125
  text "6" at 24225.48,5570.34 h125
OUTLINE:
  lines w1: 12000,10100 ccw(c12100,10100) 12100,10000 16230.71,10000 ccw(c16230.71,10100) 16330.71,10100 16330.71,12262.2 ccw(c16230.71,12262.2) 16230.71,12362.2 12100,12362.2 ccw(c12100,12262.2) 12000,12262.2 12000,10100
PIN_NUMBER:
  text "1" at 12436.8,12150 h33
  text "1" at 12436.8,12150 h33
  text "1" at 15961.8,12000 h33
  text "1" at 16111.8,10425 h33
  text "1" at 12436.8,10150 h33
  text "1" at 12436.8,10150 h33
PLACE_BOUND_TOP:
  lines w1: 12430,10130 12430,10170 12470,10170 12470,10130 12430,10130 ; 12430,12130 12430,12170 12470,12170 12470,12130 12430,12130 ; 15955,11980 15955,12020 15995,12020 15995,11980 15955,11980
